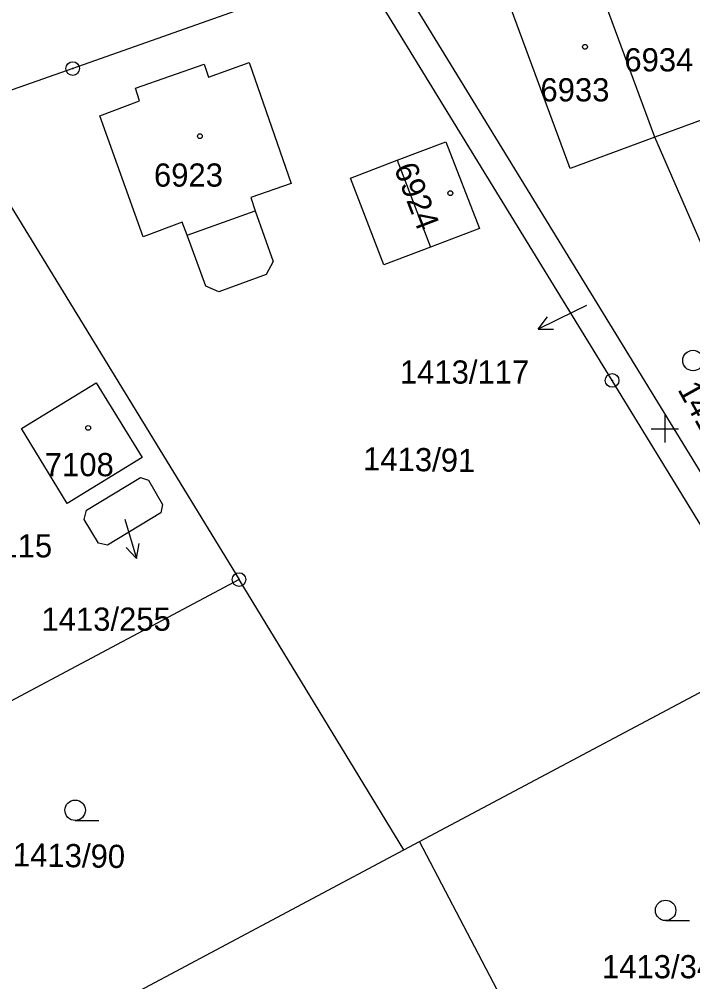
# Model space of a CAD drawing. Extents: x -771260 to -770828, y -1053564 to -1052811.
# Drawn here: x -771047.3 to -770998, y -1053090.5 to -1053020 of the extents above; entities that cross this region are included whole.
import ezdxf

# ---------------------------------------------------------------- set-up
doc = ezdxf.new("R2010")
doc.units = 0
for name, color, linetype in [('14_8_2023_krizky', 7, 'Continuous'), ('25_3_2019_krizky_JTSK', 7, 'Continuous'), ('DKM_Hranice parcel', 7, 'Continuous'), ('DKM_Parcelní čísla', 7, 'Continuous'), ('DKM_Pop  PČ popisy', 7, 'Continuous'), ('DKM_Vnitřní kresba', 7, 'Continuous'), ('DKM_Značky bodu BP', 7, 'Continuous'), ('DKM_Značky budov', 7, 'Continuous'), ('DKM_Značky kultur', 7, 'Continuous')]:
    doc.layers.add(name, color=color, linetype=linetype)

# ---------------------------------------------------------------- blocks, each defined once
blk = doc.blocks.new('KRIZEK')
at = {"layer": '25_3_2019_krizky_JTSK'}
for p, q in [((0, 10), (0, -10)), ((-10, 0), (10, 0))]:
    blk.add_line(p, q, dxfattribs=at)

msp = doc.modelspace()

# ---------------------------------------------------------------- linework, layer by layer
at = {"layer": 'DKM_Hranice parcel'}
for p, q in [((-770983.17, -1053076.38), (-771020.69, -1053015.09)), ((-771000.73, -1053028.62), (-771005.26, -1053016.33)), ((-770994.58, -1053026.36), (-771000.73, -1053028.62)), ((-771052.21, -1053026.69), (-771031.2, -1053061.05)), ((-770980.57, -1053075.02), (-771000.73, -1053028.62)), ((-771031.2, -1053061.05), (-771047.96, -1053069.99)), ((-771019.12, -1053080.86), (-771031.2, -1053061.05)), ((-771017.98, -1053080.25), (-770991.72, -1053066.27)), ((-771019.12, -1053080.86), (-771017.98, -1053080.25)), ((-771006.78, -1053101.58), (-771017.98, -1053080.25)), ((-771054.84, -1053099.89), (-771019.12, -1053080.86))]:
    msp.add_line(p, q, dxfattribs=at)
for points in [[(-771022.41, -1053016.16), (-771043.39, -1053023.58), (-771052.21, -1053026.69)], [(-770991.72, -1053066.27), (-771003.86, -1053046.45), (-771022.41, -1053016.16)], [(-771000.73, -1053028.62), (-771006.94, -1053030.91), (-771011.47, -1053018.62)], [(-771035.36, -1053034.84), (-771038.23, -1053035.93), (-771041.4, -1053027.06), (-771038.49, -1053025.94), (-771038.79, -1053025.02), (-771033.75, -1053023.25), (-771033.44, -1053024.21), (-771030.46, -1053023.13), (-771027.37, -1053032.01), (-771030.34, -1053033.03), (-771030.01, -1053034.01), (-771028.7, -1053037.73), (-771029.21, -1053038.69), (-771032.69, -1053039.94), (-771033.64, -1053039.53), (-771034.99, -1053035.79), (-771035.36, -1053034.84)], [(-771013.59, -1053035.3), (-771017.17, -1053036.68), (-771020.58, -1053037.98), (-771023.03, -1053031.61), (-771019.62, -1053030.3), (-771016.04, -1053028.96), (-771013.59, -1053035.3)], [(-771043.79, -1053055.47), (-771047.15, -1053049.96), (-771041.66, -1053046.63), (-771038.31, -1053052.1), (-771043.79, -1053055.47)], [(-771038.43, -1053053.56), (-771037.83, -1053053.77), (-771036.8, -1053055.55), (-771036.94, -1053056.16), (-771040.84, -1053058.52), (-771041.5, -1053058.37), (-771042.54, -1053056.65), (-771042.37, -1053055.96), (-771038.43, -1053053.56)]]:
    msp.add_lwpolyline(points, dxfattribs=at)
at = {"layer": 'DKM_Pop  PČ popisy'}
for p, q in [((-771005.73, -1053040.95), (-771006.59, -1053041.37)), ((-771006.59, -1053041.37), (-771009.287, -1053042.686)), ((-771009.287, -1053042.686), (-771008.607, -1053041.796)), ((-771009.287, -1053042.686), (-771008.168, -1053042.697)), ((-771039.58, -1053056.63), (-771038.703, -1053059.5)), ((-771038.703, -1053059.5), (-771039.474, -1053058.689)), ((-771038.703, -1053059.5), (-771038.517, -1053058.396))]:
    msp.add_line(p, q, dxfattribs=at)
at = {"layer": 'DKM_Vnitřní kresba'}
for p, q in [((-771019.62, -1053030.3), (-771017.17, -1053036.68)), ((-771034.99, -1053035.79), (-771030.01, -1053034.01))]:
    msp.add_line(p, q, dxfattribs=at)
at = {"layer": 'DKM_Značky bodu BP'}
for centre, radius in [((-771043.39, -1053023.58), 0.5), ((-771043.39, -1053023.58), 0.0303), ((-771003.86, -1053046.45), 0.5), ((-771003.86, -1053046.45), 0.0303), ((-771031.2, -1053061.05), 0.5), ((-771031.2, -1053061.05), 0.0303)]:
    msp.add_circle(centre, radius, dxfattribs=at)
at = {"layer": 'DKM_Značky budov'}
for centre in [(-771005.847, -1053021.989), (-771034.067, -1053028.539), (-771015.717, -1053032.719), (-771042.257, -1053049.929)]:
    msp.add_circle(centre, 0.175, dxfattribs=at)
at = {"layer": 'DKM_Značky kultur'}
for p, q in [((-771043.213, -1053078.71), (-771041.463, -1053078.71)), ((-770999.943, -1053086.05), (-770998.193, -1053086.05))]:
    msp.add_line(p, q, dxfattribs=at)
for centre in [(-770997.933, -1053044.99), (-771043.213, -1053077.96), (-770999.943, -1053085.3)]:
    msp.add_circle(centre, 0.75, dxfattribs=at)

# ---------------------------------------------------------------- block references
at = {"layer": '14_8_2023_krizky', "xscale": 0.1, "yscale": 0.10000000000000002}
msp.add_blockref('KRIZEK', (-771000, -1053050), dxfattribs=at)

# ---------------------------------------------------------------- texts
at = {"layer": 'DKM_Parcelní čísla'}
for s, p in [('6934', (-771002.964, -1053023.79)), ('6933', (-771009.114, -1053025.989)), ('6923', (-771037.434, -1053032.239)), ('1413/117', (-771019.415, -1053046.68)), ('7108', (-771045.434, -1053053.47)), ('1413/115', (-771054.375, -1053059.42)), ('1413/255', (-771045.68, -1053064.798)), ('1413/345', (-771004.605, -1053090.279))]:
    msp.add_text(s, height=1.7, dxfattribs=at).set_placement(p)
for s, rotation, p in [('6924', 291, (-771019.869, -1053030.867)), ('1413/118', 299, (-770999.096, -1053047.103)), ('1413/91', 359, (-771022.12, -1053053.029)), ('1413/90', 359, (-771047.78, -1053082.059))]:
    msp.add_text(s, height=1.7, rotation=rotation, dxfattribs=at).set_placement(p)

doc.saveas('drawing.dxf')
